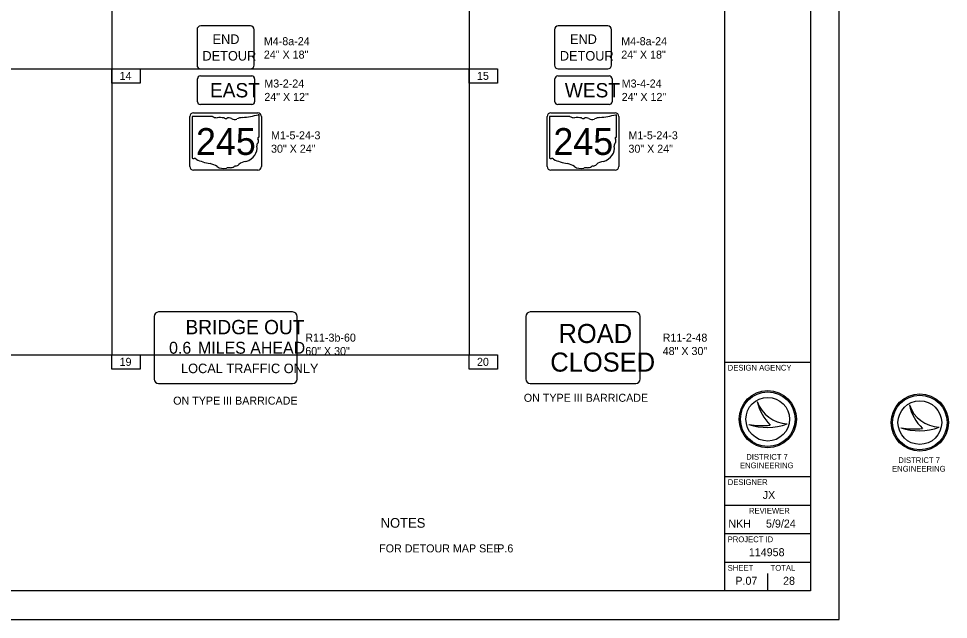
# Model space of a CAD drawing. Extents: x 0 to 718, y 0 to 440.
# Drawn here: x 393 to 718.2, y 0 to 210.1 of the extents above; entities that cross this region are included whole.
import ezdxf

# ---------------------------------------------------------------- set-up
doc = ezdxf.new("R2010")
doc.units = 0
for name, color, linetype in [('SC_Scratch1', 7, 'Continuous'), ('SH_Border', 7, 'Continuous'), ('SH_Cut_Line', 7, 'Continuous'), ('SH_Data', 7, 'Continuous'), ('SH_Text', 7, 'Continuous'), ('SN_P_Signs', 7, 'Continuous'), ('SN_P_Text', 7, 'Continuous')]:
    doc.layers.add(name, color=color, linetype=linetype)

msp = doc.modelspace()

# ---------------------------------------------------------------- linework, layer by layer
at = {"layer": 'SC_Scratch1'}
for p, q in [((425.54, 292.53), (425.54, 192.53)), ((550.54, 292.53), (550.54, 192.53)), ((375.54, 192.53), (550.54, 192.53)), ((425.54, 192.53), (425.54, 92.53)), ((550.54, 192.53), (550.54, 92.53)), ((375.54, 92.53), (550.54, 92.53))]:
    msp.add_line(p, q, dxfattribs=at)
at = {"layer": 'SH_Border'}
for p, q in [((640, 10), (640, 430)), ((640, 90), (670, 90)), ((640, 50), (670, 50)), ((640, 40), (670, 40)), ((640, 30), (670, 30)), ((640, 20), (670, 20))]:
    msp.add_line(p, q, dxfattribs=at)
msp.add_lwpolyline([(30, 430), (670, 430), (670, 10), (30, 10)], close=True, dxfattribs=at)
at = {"layer": 'SH_Cut_Line'}
msp.add_lwpolyline([(0, 0), (680, 0), (680, 440), (0, 440)], close=True, dxfattribs=at)
at = {"layer": 'SH_Data'}
for p, q in [((651.35, 76.19), (651.35, 76.19)), ((704.54, 75.02), (704.54, 75.02)), ((655, 70), (655, 70)), ((661.75, 68.37), (661.75, 68.37)), ((648.34, 68.19), (648.34, 68.19)), ((701.53, 67.02), (701.53, 67.02)), ((714.93, 67.2), (714.93, 67.2)), ((647.5, 13.5), (647.5, 13.5)), ((655, 10), (655, 16))]:
    msp.add_line(p, q, dxfattribs=at)
for centre, radius in [((655, 70), 10), ((655, 70), 9.54), ((655, 70), 9.54), ((708.19, 68.83), 10), ((708.19, 68.83), 9.54), ((708.19, 68.83), 9.54), ((655, 70), 7.64), ((708.19, 68.83), 7.64)]:
    msp.add_circle(centre, radius, dxfattribs=at)
for centre, radius, start, end in [((662.32, 79.95), 11.6, 198.9257, 198.9319), ((666.93, 79.4), 15.91, 191.6379, 191.6421), ((662.32, 79.95), 11.6, 198.9319, 267.1657), ((666.93, 79.4), 15.91, 191.6421, 226.0947), ((715.5, 78.78), 11.6, 198.9257, 198.9319), ((720.12, 78.23), 15.91, 191.6379, 191.6421), ((715.5, 78.78), 11.6, 198.9319, 267.1657), ((720.12, 78.23), 15.91, 191.6421, 226.0947), ((654.79, 87.4), 20.26, 251.4576, 290.0832), ((652.96, 93.09), 25.32, 259.4964, 259.4995), ((654.79, 87.4), 20.26, 251.4527, 251.4576), ((652.96, 93.09), 25.32, 259.4995, 276.6672), ((707.97, 86.23), 20.26, 251.4576, 290.0832), ((706.15, 91.91), 25.32, 259.4964, 259.4995), ((707.97, 86.23), 20.26, 251.4527, 251.4576), ((706.15, 91.91), 25.32, 259.4995, 276.6672)]:
    msp.add_arc(centre, radius, start, end, dxfattribs=at)
at = {"layer": 'SH_Text'}
for points in [[(425.54, 192.53), (435.54, 192.53), (435.54, 187.53), (425.54, 187.53)], [(550.54, 192.53), (560.54, 192.53), (560.54, 187.53), (550.54, 187.53)], [(425.54, 92.53), (435.54, 92.53), (435.54, 87.53), (425.54, 87.53)], [(550.54, 92.53), (560.54, 92.53), (560.54, 87.53), (550.54, 87.53)]]:
    msp.add_lwpolyline(points, close=True, dxfattribs=at)
at = {"layer": 'SN_P_Signs'}
for p, q in [((455.55, 181.03), (455.55, 189.03)), ((456.55, 190.03), (474.55, 190.03)), ((475.55, 189.03), (475.55, 181.03)), ((580.55, 181.03), (580.55, 189.03)), ((581.55, 190.03), (599.55, 190.03)), ((600.55, 189.03), (600.55, 181.03)), ((474.55, 180.03), (456.55, 180.03)), ((599.55, 180.03), (581.55, 180.03)), ((453.67, 175.64), (453.67, 161.41)), ((460.76, 175.88), (453.9, 175.88)), ((477.11, 168.79), (477.11, 176.24)), ((578.67, 175.64), (578.67, 161.41)), ((585.76, 175.88), (578.9, 175.88)), ((602.11, 168.79), (602.11, 176.24)), ((477.1, 168.79), (477.11, 168.79)), ((602.1, 168.79), (602.11, 168.79))]:
    msp.add_line(p, q, dxfattribs=at)
for points in [[(455.39, 206.19), (455.39, 193.79)], [(474.09, 207.49), (456.69, 207.49)], [(475.39, 193.79), (475.39, 206.19)], [(580.39, 206.19), (580.39, 193.79)], [(599.09, 207.49), (581.69, 207.49)], [(600.39, 193.79), (600.39, 206.19)], [(456.69, 192.49), (474.09, 192.49)], [(581.69, 192.49), (599.09, 192.49)], [(452.89, 158.36), (452.89, 175.86)], [(454.14, 177.11), (476.64, 177.11)], [(477.89, 175.86), (477.89, 158.36)], [(577.89, 158.36), (577.89, 175.86)], [(579.14, 177.11), (601.64, 177.11)], [(602.89, 175.86), (602.89, 158.36)], [(476.64, 157.11), (454.14, 157.11)], [(601.64, 157.11), (579.14, 157.11)], [(488.83, 107.49), (441.95, 107.49)], [(608.82, 107.49), (571.95, 107.49)], [(440.39, 105.93), (440.39, 84.05)], [(490.39, 84.05), (490.39, 105.93)], [(570.39, 105.92), (570.39, 84.06)], [(610.39, 84.06), (610.39, 105.92)], [(441.95, 82.49), (488.83, 82.49)], [(571.95, 82.49), (608.82, 82.49)]]:
    msp.add_lwpolyline(points, dxfattribs=at)
for centre, radius, start, end in [((456.69, 206.19), 1.3, 90, 180), ((474.09, 206.19), 1.3, 0, 90), ((581.69, 206.19), 1.3, 90, 180), ((599.09, 206.19), 1.3, 0, 90), ((456.69, 193.79), 1.3, 180, 270), ((474.09, 193.79), 1.3, 270, 0), ((581.69, 193.79), 1.3, 180, 270), ((599.09, 193.79), 1.3, 270, 0), ((456.55, 189.03), 1, 90, 180), ((474.55, 189.03), 1, 0, 90), ((581.55, 189.03), 1, 90, 180), ((599.55, 189.03), 1, 0, 90), ((456.55, 181.03), 1, 180, 270), ((474.55, 181.03), 1, 270, 0), ((581.55, 181.03), 1, 180, 270), ((599.55, 181.03), 1, 270, 0), ((454.14, 175.86), 1.25, 90, 180), ((476.64, 175.86), 1.25, 0, 90), ((579.14, 175.86), 1.25, 90, 180), ((601.64, 175.86), 1.25, 0, 90), ((454.14, 158.36), 1.25, 180, 270), ((476.64, 158.36), 1.25, 270, 0), ((579.14, 158.36), 1.25, 180, 270), ((601.64, 158.36), 1.25, 270, 0), ((441.95, 105.93), 1.56, 90, 180), ((488.83, 105.93), 1.56, 0, 90), ((571.95, 105.92), 1.57, 90, 180), ((608.82, 105.92), 1.57, 0, 90), ((441.95, 84.05), 1.56, 180, 270), ((488.83, 84.05), 1.56, 270, 0), ((571.95, 84.06), 1.57, 180, 270), ((608.82, 84.06), 1.57, 270, 0)]:
    msp.add_arc(centre, radius, start, end, dxfattribs=at)
for centre, major_axis, start_param, end_param in [((453.94, 175.67), (0.272, 0), 1.712693, 3.28349), ((462.4, 177.54), (2.63, 0), 4.042523, 4.731795), ((468.76, 195.29), (24.85, 0), 4.814394, 5.042369), ((476.85, 176.27), (0.261, 0), 6.141152, 7.989035), ((578.94, 175.67), (0.272, 0), 1.712693, 3.28349), ((587.4, 177.54), (2.63, 0), 4.042523, 4.731795), ((593.76, 195.29), (24.85, 0), 4.814394, 5.042369), ((601.85, 176.27), (0.261, 0), 6.141152, 7.989035), ((463.27, 167.89), (9.45, 0), 1.404758, 1.657858), ((465.42, 175.74), (0.76, 0), 3.836095, 5.185415), ((466.53, 174.1), (1.58, 0), 0.950623, 2.079405), ((468.57, 176.35), (1.9, 0), 4.081561, 5.145723), ((471.93, 171.54), (5, 0), 1.699011, 2.107814), ((588.27, 167.89), (9.45, 0), 1.404758, 1.657858), ((590.42, 175.74), (0.76, 0), 3.836095, 5.185415), ((591.53, 174.1), (1.58, 0), 0.950623, 2.079405), ((593.57, 176.35), (1.9, 0), 4.081561, 5.145723), ((596.93, 171.54), (5, 0), 1.699011, 2.107814), ((478.04, 165.68), (1.76, 0), 2.387724, 3.262537), ((477.05, 168.25), (0.404, 0), 1.883978, 3.671073), ((474.48, 167.3), (2.42, 0), 5.934695, 6.695948), ((476.83, 168.76), (0.279, 0), 5.05454, 6.418171), ((603.04, 165.68), (1.76, 0), 2.387724, 3.262537), ((602.05, 168.25), (0.404, 0), 1.883978, 3.671073), ((599.48, 167.3), (2.42, 0), 5.934695, 6.695948), ((601.83, 168.76), (0.279, 0), 5.05454, 6.418171), ((470.15, 164.73), (6.22, 0), 5.101752, 6.440018), ((595.15, 164.73), (6.22, 0), 5.101752, 6.440018), ((453.94, 161.38), (0.274, 0), 3.00124, 4.508301), ((453.98, 162.83), (2.09, 0), 4.665946, 4.897461), ((454.41, 160.59), (0.754, 0), 0.519207, 1.627899), ((463.93, 173.37), (17.95, 0), 4.195997, 4.488961), ((458.57, 155.01), (5.62, 0), 0.823519, 1.323587), ((472.77, 157.41), (3.4, 0), 1.647645, 2.488434), ((578.94, 161.38), (0.274, 0), 3.00124, 4.508301), ((578.98, 162.83), (2.09, 0), 4.665946, 4.897461), ((579.41, 160.59), (0.754, 0), 0.519207, 1.627899), ((588.93, 173.37), (17.95, 0), 4.195997, 4.488961), ((583.57, 155.01), (5.62, 0), 0.823519, 1.323587), ((597.77, 157.41), (3.4, 0), 1.647645, 2.488434), ((464.65, 160.52), (3.56, 0), 4.026481, 4.996735), ((466.71, 155.6), (2.93, 0), 1.495662, 1.94098), ((466.97, 159.45), (1.9, 0), 4.691044, 5.507374), ((468.69, 158.07), (0.535, 0), 1.147584, 2.315152), ((468.46, 160.03), (2.01, 0), 4.937069, 5.64225), ((589.65, 160.52), (3.56, 0), 4.026481, 4.996735), ((591.71, 155.6), (2.93, 0), 1.495662, 1.94098), ((591.97, 159.45), (1.9, 0), 4.691044, 5.507374), ((593.69, 158.07), (0.535, 0), 1.147584, 2.315152), ((593.46, 160.03), (2.01, 0), 4.937069, 5.64225)]:
    msp.add_ellipse(centre, major_axis=major_axis, ratio=0.8, start_param=start_param, end_param=end_param, dxfattribs=at)

# ---------------------------------------------------------------- texts
at = {"layer": 'SH_Data'}
for s, height, p in [('DESIGN AGENCY', 2, (641, 87)), ('DESIGNER', 2, (641, 47)), ('JX', 2.8, (653.23, 42.1)), ('REVIEWER', 2, (648.44, 37)), ('NKH', 2.8, (641.24, 32.1)), ('5/9/24', 2.8, (654.39, 32.1)), ('PROJECT ID', 2, (641, 27)), ('114958', 2.8, (648.39, 22.1)), ('SHEET', 2, (641, 17)), ('TOTAL', 2, (656, 17)), ('P.07', 2.8, (643.67, 12.1)), ('28', 2.8, (660.36, 12.1))]:
    msp.add_text(s, height=height, dxfattribs=at).set_placement(p)
at = {"layer": 'SH_Text'}
for s, height, p in [('14', 2.8, (428.31, 188.66)), ('15', 2.8, (553.31, 188.66)), ('19', 2.8, (428.31, 88.66)), ('20', 2.8, (553.31, 88.66)), ('DISTRICT 7', 2, (647.48, 55.85)), ('DISTRICT 7', 2, (700.67, 54.68)), ('ENGINEERING', 2, (645.3, 52.85)), ('ENGINEERING', 2, (698.49, 51.68)), ('NOTES', 3.4, (519.61, 32.05)), ('FOR DETOUR MAP SEE', 2.8, (519.1, 23.43)), ('P.6', 2.8, (560.4, 23.43))]:
    msp.add_text(s, height=height, dxfattribs=at).set_placement(p)
at = {"layer": 'SN_P_Signs'}
for s, height, p in [('END', 3.333, (460.83, 201.22)), ('END', 3.333, (585.83, 201.22)), ('DETOUR', 3.333, (457.29, 195.4)), ('DETOUR', 3.333, (582.29, 195.4)), ('EAST', 5, (459.91, 182.53)), ('WEST', 5, (584.02, 182.53)), ('245', 9.375, (455.03, 162.41)), ('245', 9.375, (580.03, 162.41)), ('BRIDGE OUT', 5, (451.36, 99.71)), ('ROAD', 6.667, (581.81, 96.64)), ('0.6', 4.167, (445.62, 92.9)), ('MILES AHEAD', 4.1667, (455.74, 92.9)), ('CLOSED', 6.667, (578.95, 86.64)), ('LOCAL TRAFFIC ONLY', 3.3333, (449.81, 86.1))]:
    msp.add_text(s, height=height, dxfattribs=at).set_placement(p)
at = {"layer": 'SN_P_Text'}
for s, p in [('M4-8a-24', (478.77, 200.78)), ('M4-8a-24', (603.77, 200.78)), ('24" X 18"', (478.77, 196.09)), ('24" X 18"', (603.77, 196.09)), ('M3-2-24', (478.93, 185.98)), ('M3-4-24', (603.93, 185.98)), ('24" X 12"', (478.93, 181.29)), ('24" X 12"', (603.93, 181.29)), ('M1-5-24-3', (481.28, 167.87)), ('M1-5-24-3', (606.28, 167.87)), ('30" X 24"', (481.28, 163.18)), ('30" X 24"', (606.28, 163.18)), ('R11-3b-60', (493.26, 97.13)), ('R11-2-48', (618.26, 97.13)), ('60" X 30"', (493.26, 92.44)), ('48" X 30"', (618.26, 92.44)), ('ON TYPE III BARRICADE', (569.69, 76.09)), ('ON TYPE III BARRICADE', (447.06, 75.09))]:
    msp.add_text(s, height=2.8, dxfattribs=at).set_placement(p)

doc.saveas('drawing.dxf')
